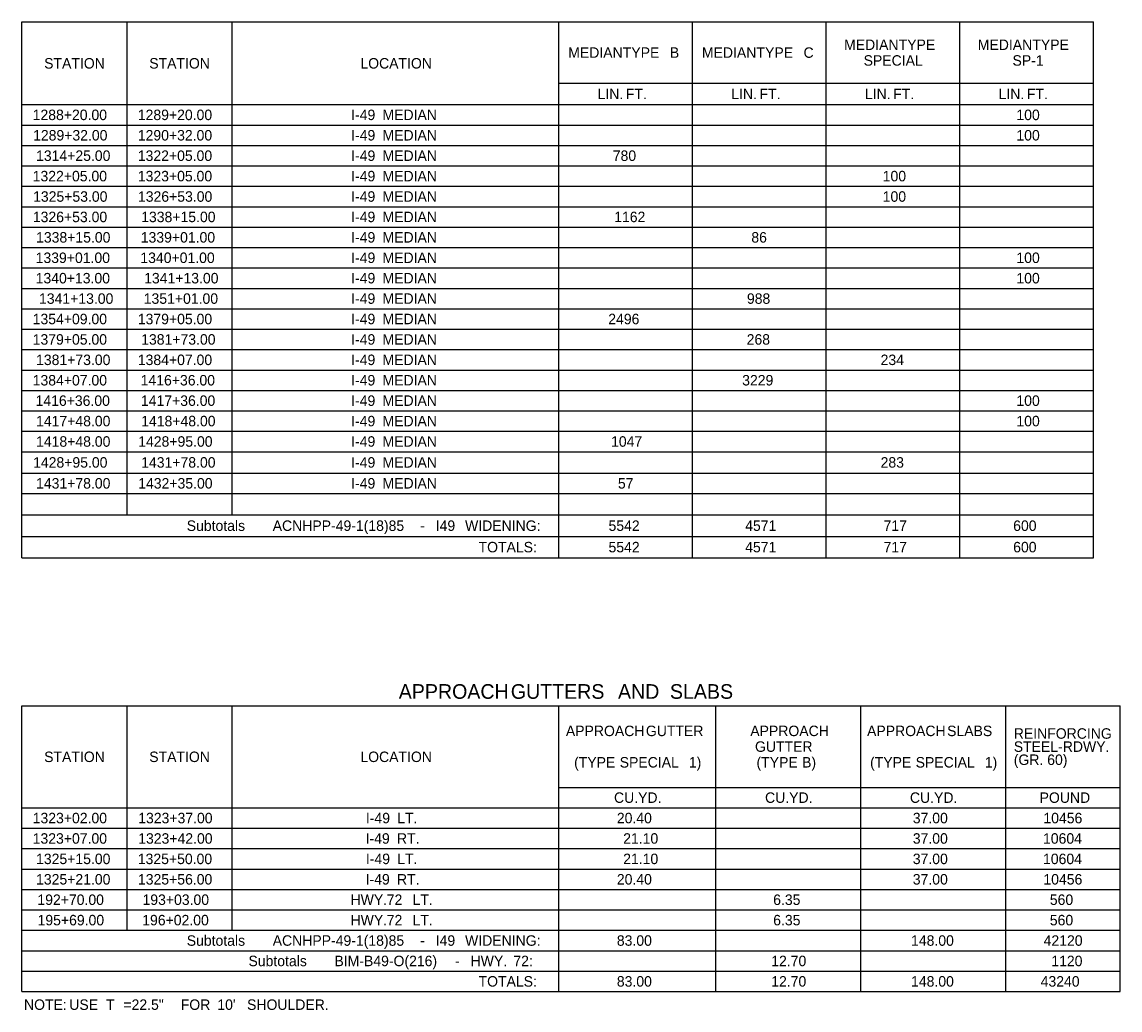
# Model space of a CAD drawing. Extents: x 1226589 to 1228130, y 151309 to 152305.
# Drawn here: x 1226589 to 1227113, y 151369 to 151841 of the extents above; entities that cross this region are included whole.
import ezdxf

# ---------------------------------------------------------------- set-up
doc = ezdxf.new("R2010")
doc.units = 0
doc.layers.add('R_Dimension', color=7, linetype='Continuous')

msp = doc.modelspace()

# ---------------------------------------------------------------- linework, layer by layer
at = {"layer": 'R_Dimension'}
for p, q in [((1226588.59, 151840.88), (1227100.46, 151840.88)), ((1226588.59, 151584.94), (1226588.59, 151840.88)), ((1226638.8, 151605.41), (1226638.8, 151840.88)), ((1226689.01, 151605.41), (1226689.01, 151840.88)), ((1226845.01, 151584.94), (1226845.01, 151840.88)), ((1226908.87, 151584.94), (1226908.87, 151840.88)), ((1226972.74, 151584.94), (1226972.74, 151840.88)), ((1227036.6, 151584.94), (1227036.6, 151840.88)), ((1227100.46, 151584.94), (1227100.46, 151840.88)), ((1226845.01, 151811.63), (1227100.46, 151811.63)), ((1226588.59, 151801.39), (1227100.46, 151801.39)), ((1226588.59, 151791.64), (1227100.46, 151791.64)), ((1226588.59, 151781.89), (1227100.46, 151781.89)), ((1226588.59, 151772.14), (1227100.46, 151772.14)), ((1226588.59, 151762.39), (1227100.46, 151762.39)), ((1226588.59, 151752.64), (1227100.46, 151752.64)), ((1226588.59, 151742.89), (1227100.46, 151742.89)), ((1226588.59, 151733.14), (1227100.46, 151733.14)), ((1226588.59, 151723.39), (1227100.46, 151723.39)), ((1226588.59, 151713.64), (1227100.46, 151713.64)), ((1226588.59, 151703.89), (1227100.46, 151703.89)), ((1226588.59, 151694.14), (1227100.46, 151694.14)), ((1226588.59, 151684.39), (1227100.46, 151684.39)), ((1226588.59, 151674.64), (1227100.46, 151674.64)), ((1226588.59, 151664.89), (1227100.46, 151664.89)), ((1226588.59, 151655.14), (1227100.46, 151655.14)), ((1226588.59, 151645.39), (1227100.46, 151645.39)), ((1226588.59, 151635.64), (1227100.46, 151635.64)), ((1226588.59, 151625.4), (1227100.46, 151625.4)), ((1226588.59, 151615.65), (1227100.46, 151615.65)), ((1226588.59, 151605.41), (1227100.46, 151605.41)), ((1226588.59, 151595.18), (1227100.46, 151595.18)), ((1226588.59, 151584.94), (1227100.46, 151584.94)), ((1226588.59, 151514.29), (1227113.14, 151514.29)), ((1226588.59, 151377.79), (1226588.59, 151514.29)), ((1226638.8, 151407.04), (1226638.8, 151514.29)), ((1226689.01, 151407.04), (1226689.01, 151514.29)), ((1226845.01, 151377.79), (1226845.01, 151514.29)), ((1226920.09, 151377.79), (1226920.09, 151514.29)), ((1226989.31, 151377.79), (1226989.31, 151514.29)), ((1227058.54, 151377.79), (1227058.54, 151514.29)), ((1227113.14, 151377.79), (1227113.14, 151514.29)), ((1226845.01, 151475.29), (1227113.14, 151475.29)), ((1226588.59, 151465.54), (1227113.14, 151465.54)), ((1226588.59, 151455.79), (1227113.14, 151455.79)), ((1226588.59, 151446.04), (1227113.14, 151446.04)), ((1226588.59, 151436.29), (1227113.14, 151436.29)), ((1226588.59, 151426.54), (1227113.14, 151426.54)), ((1226588.59, 151416.79), (1227113.14, 151416.79)), ((1226588.59, 151407.04), (1227113.14, 151407.04)), ((1226588.59, 151397.29), (1227113.14, 151397.29)), ((1226588.59, 151387.54), (1227113.14, 151387.54)), ((1226588.59, 151377.79), (1227113.14, 151377.79))]:
    msp.add_line(p, q, dxfattribs=at)

# ---------------------------------------------------------------- texts
for s, height, p in [('MEDIAN', 5, (1226981.32, 151827.5)), (' TYPE', 5, (1227005.53, 151827.5)), ('MEDIAN', 5, (1227045.18, 151827.5)), (' TYPE', 5, (1227069.4, 151827.5)), ('MEDIAN', 5, (1226849.54, 151823.75)), (' TYPE', 5, (1226873.75, 151823.75)), (' B', 5, (1226896.23, 151823.75)), ('MEDIAN', 5, (1226913.4, 151823.75)), (' TYPE', 5, (1226937.62, 151823.75)), (' C', 5, (1226960.1, 151823.75)), ('STATION', 5, (1226599.19, 151818.63)), ('STATION', 5, (1226649.4, 151818.63)), ('LOCATION', 5, (1226750.26, 151818.63)), ('SPECIAL', 5, (1226990.65, 151820)), ('SP-1', 5, (1227061.76, 151820)), ('LIN.', 5, (1226863.54, 151804.01)), (' FT.', 5, (1226875.19, 151804.01)), ('LIN.', 5, (1226927.4, 151804.01)), (' FT.', 5, (1226939.05, 151804.01)), ('LIN.', 5, (1226991.26, 151804.01)), (' FT.', 5, (1227002.92, 151804.01)), ('LIN.', 5, (1227055.13, 151804.01)), (' FT.', 5, (1227066.78, 151804.01)), ('1288+20.00', 5, (1226593.71, 151794.01)), ('1289+20.00', 5, (1226643.93, 151794.01)), ('I-49', 5, (1226745.85, 151794.01)), (' MEDIAN', 5, (1226758.96, 151794.01)), ('100', 5, (1227063.63, 151794.01)), ('1289+32.00', 5, (1226593.91, 151784.26)), ('1290+32.00', 5, (1226643.93, 151784.26)), ('I-49', 5, (1226745.85, 151784.26)), (' MEDIAN', 5, (1226758.96, 151784.26)), ('100', 5, (1227063.63, 151784.26)), ('1314+25.00', 5, (1226595.33, 151774.51)), ('1322+05.00', 5, (1226643.93, 151774.51)), ('I-49', 5, (1226745.85, 151774.51)), (' MEDIAN', 5, (1226758.96, 151774.51)), ('780', 5, (1226870.82, 151774.51)), ('1322+05.00', 5, (1226593.71, 151764.76)), ('1323+05.00', 5, (1226643.93, 151764.76)), ('I-49', 5, (1226745.85, 151764.76)), (' MEDIAN', 5, (1226758.96, 151764.76)), ('100', 5, (1226999.77, 151764.76)), ('1325+53.00', 5, (1226593.91, 151755.01)), ('1326+53.00', 5, (1226644, 151755.01)), ('I-49', 5, (1226745.85, 151755.01)), (' MEDIAN', 5, (1226758.96, 151755.01)), ('100', 5, (1226999.77, 151755.01)), ('1326+53.00', 5, (1226593.79, 151745.26)), ('1338+15.00', 5, (1226645.54, 151745.26)), ('I-49', 5, (1226745.85, 151745.26)), (' MEDIAN', 5, (1226758.96, 151745.26)), ('1162', 5, (1226871.51, 151745.26)), ('1338+15.00', 5, (1226595.33, 151735.51)), ('1339+01.00', 5, (1226645.34, 151735.51)), ('I-49', 5, (1226745.85, 151735.51)), (' MEDIAN', 5, (1226758.96, 151735.51)), ('86', 5, (1226937.01, 151735.51)), ('1339+01.00', 5, (1226595.13, 151725.76)), ('1340+01.00', 5, (1226645.15, 151725.76)), ('I-49', 5, (1226745.85, 151725.76)), (' MEDIAN', 5, (1226758.96, 151725.76)), ('100', 5, (1227063.63, 151725.76)), ('1340+13.00', 5, (1226595.13, 151716.01)), ('1341+13.00', 5, (1226646.96, 151716.01)), ('I-49', 5, (1226745.85, 151716.01)), (' MEDIAN', 5, (1226758.96, 151716.01)), ('100', 5, (1227063.63, 151716.01)), ('1341+13.00', 5, (1226596.74, 151706.26)), ('1351+01.00', 5, (1226646.76, 151706.26)), ('I-49', 5, (1226745.85, 151706.26)), (' MEDIAN', 5, (1226758.96, 151706.26)), ('988', 5, (1226934.9, 151706.26)), ('1354+09.00', 5, (1226593.71, 151696.51)), ('1379+05.00', 5, (1226643.93, 151696.51)), ('I-49', 5, (1226745.85, 151696.51)), (' MEDIAN', 5, (1226758.96, 151696.51)), ('2496', 5, (1226868.66, 151696.51)), ('1379+05.00', 5, (1226593.71, 151686.76)), ('1381+73.00', 5, (1226645.54, 151686.76)), ('I-49', 5, (1226745.85, 151686.76)), (' MEDIAN', 5, (1226758.96, 151686.76)), ('268', 5, (1226934.78, 151686.76)), ('1381+73.00', 5, (1226595.33, 151677.01)), ('1384+07.00', 5, (1226643.93, 151677.01)), ('I-49', 5, (1226745.85, 151677.01)), (' MEDIAN', 5, (1226758.96, 151677.01)), ('234', 5, (1226998.76, 151677.01)), ('1384+07.00', 5, (1226593.71, 151667.26)), ('1416+36.00', 5, (1226645.3, 151667.26)), ('I-49', 5, (1226745.85, 151667.26)), (' MEDIAN', 5, (1226758.96, 151667.26)), ('3229', 5, (1226932.64, 151667.26)), ('1416+36.00', 5, (1226595.09, 151657.51)), ('1417+36.00', 5, (1226645.42, 151657.51)), ('I-49', 5, (1226745.85, 151657.51)), (' MEDIAN', 5, (1226758.96, 151657.51)), ('100', 5, (1227063.63, 151657.51)), ('1417+48.00', 5, (1226595.33, 151647.76)), ('1418+48.00', 5, (1226645.54, 151647.76)), ('I-49', 5, (1226745.85, 151647.76)), (' MEDIAN', 5, (1226758.96, 151647.76)), ('100', 5, (1227063.63, 151647.76)), ('1418+48.00', 5, (1226595.33, 151638.01)), ('1428+95.00', 5, (1226644.12, 151638.01)), ('I-49', 5, (1226745.85, 151638.01)), (' MEDIAN', 5, (1226758.96, 151638.01)), ('1047', 5, (1226870.01, 151638.01)), ('1428+95.00', 5, (1226593.91, 151628.02)), ('1431+78.00', 5, (1226645.54, 151628.02)), ('I-49', 5, (1226745.85, 151628.02)), (' MEDIAN', 5, (1226758.96, 151628.02)), ('283', 5, (1226998.76, 151628.02)), ('1431+78.00', 5, (1226595.33, 151618.03)), ('1432+35.00', 5, (1226644.12, 151618.03)), ('I-49', 5, (1226745.85, 151618.03)), (' MEDIAN', 5, (1226758.96, 151618.03)), ('57', 5, (1226873.28, 151618.03)), ('Subtotals', 5, (1226667.3, 151597.8)), (' ACNHPP-49-1(18)85', 5, (1226706.51, 151597.8)), (' I49', 5, (1226784.39, 151597.8)), (' WIDENING:', 5, (1226798.4, 151597.8)), ('5542', 5, (1226868.79, 151597.8)), ('4571', 5, (1226934.07, 151597.8)), ('717', 5, (1227000.18, 151597.8)), ('600', 5, (1227062.09, 151597.8)), (' -', 5, (1226776.95, 151597.8)), ('TOTALS:', 5, (1226806.71, 151587.56)), ('5542', 5, (1226868.79, 151587.56)), ('4571', 5, (1226934.07, 151587.56)), ('717', 5, (1227000.18, 151587.56)), ('600', 5, (1227062.09, 151587.56)), ('APPROACH', 7, (1226768.57, 151517.61)), (' GUTTERS', 7, (1226819.5, 151517.61)), (' AND', 7, (1226870.7, 151517.61)), (' SLABS', 7, (1226895.51, 151517.61)), ('APPROACH', 5, (1226848.42, 151499.79)), (' GUTTER', 5, (1226884.79, 151499.79)), ('APPROACH', 5, (1226936.51, 151499.79)), ('APPROACH', 5, (1226992.29, 151499.79)), (' SLABS', 5, (1227028.67, 151499.79)), ('REINFORCING', 5, (1227062.38, 151498.54)), ('GUTTER', 5, (1226938.76, 151492.29)), ('STEEL-RDWY.', 5, (1227062.38, 151492.28)), ('STATION', 5, (1226599.19, 151487.41)), ('STATION', 5, (1226649.4, 151487.41)), ('LOCATION', 5, (1226750.26, 151487.41)), ('(TYPE', 5, (1226852.35, 151484.79)), (' 1)', 5, (1226905.31, 151484.79)), ('(TYPE', 5, (1226939.48, 151484.79)), (' B)', 5, (1226959.4, 151484.79)), ('(TYPE', 5, (1226993.73, 151484.79)), (' 1)', 5, (1227046.68, 151484.79)), ('(GR. 60)', 5, (1227062.38, 151486.02)), (' SPECIAL', 5, (1226872.27, 151484.79)), (' SPECIAL', 5, (1227013.65, 151484.79)), ('CU.YD.', 5, (1226871.41, 151467.91)), ('CU.YD.', 5, (1226943.56, 151467.91)), ('CU.YD.', 5, (1227012.78, 151467.91)), ('POUND', 5, (1227074.72, 151467.91)), ('1323+02.00', 5, (1226593.71, 151458.16)), ('1323+37.00', 5, (1226644.12, 151458.16)), ('I-49', 5, (1226752.88, 151458.16)), (' LT.', 5, (1226765.99, 151458.16)), ('20.40', 5, (1226872.77, 151458.16)), ('37.00', 5, (1227014.14, 151458.16)), ('10456', 5, (1227076.53, 151458.16)), ('1323+07.00', 5, (1226593.71, 151448.41)), ('1323+42.00', 5, (1226644.12, 151448.41)), ('I-49', 5, (1226752.76, 151448.41)), (' RT.', 5, (1226765.87, 151448.41)), ('21.10', 5, (1226875.8, 151448.41)), ('37.00', 5, (1227014.14, 151448.41)), ('10604', 5, (1227076.35, 151448.41)), ('1325+15.00', 5, (1226595.33, 151438.66)), ('1325+50.00', 5, (1226643.93, 151438.66)), ('I-49', 5, (1226752.88, 151438.66)), (' LT.', 5, (1226765.99, 151438.66)), ('21.10', 5, (1226875.8, 151438.66)), ('37.00', 5, (1227014.14, 151438.66)), ('10604', 5, (1227076.35, 151438.66)), ('1325+21.00', 5, (1226595.33, 151428.91)), ('1325+56.00', 5, (1226644, 151428.91)), ('I-49', 5, (1226752.76, 151428.91)), (' RT.', 5, (1226765.87, 151428.91)), ('20.40', 5, (1226872.77, 151428.91)), ('37.00', 5, (1227014.14, 151428.91)), ('10456', 5, (1227076.53, 151428.91)), ('192+70.00', 5, (1226595.96, 151419.16)), ('193+03.00', 5, (1226646.17, 151419.16)), ('HWY.', 5, (1226745.56, 151419.16)), (' 72', 5, (1226760.99, 151419.16)), (' LT.', 5, (1226773.31, 151419.16)), ('6.35', 5, (1226947.46, 151419.16)), ('560', 5, (1227079.6, 151419.16)), ('195+69.00', 5, (1226596.04, 151409.41)), ('196+02.00', 5, (1226646.05, 151409.41)), ('HWY.', 5, (1226745.56, 151409.41)), (' 72', 5, (1226760.99, 151409.41)), (' LT.', 5, (1226773.31, 151409.41)), ('6.35', 5, (1226947.46, 151409.41)), ('560', 5, (1227079.6, 151409.41)), ('Subtotals', 5, (1226667.3, 151399.66)), (' ACNHPP-49-1(18)85', 5, (1226706.51, 151399.66)), (' -', 5, (1226776.95, 151399.66)), (' I49', 5, (1226784.39, 151399.66)), (' WIDENING:', 5, (1226798.4, 151399.66)), ('83.00', 5, (1226872.77, 151399.66)), ('148.00', 5, (1227013.31, 151399.66)), ('42120', 5, (1227076.64, 151399.66)), ('Subtotals', 5, (1226696.79, 151389.91)), (' BIM-B49-O(216)', 5, (1226736, 151389.91)), (' -', 5, (1226793.6, 151389.91)), (' HWY.', 5, (1226801.04, 151389.91)), (' 72:', 5, (1226821.47, 151389.91)), ('12.70', 5, (1226946.53, 151389.91)), ('1120', 5, (1227080.31, 151389.91)), ('TOTALS:', 5, (1226806.71, 151380.16)), ('83.00', 5, (1226872.77, 151380.16)), ('12.70', 5, (1226946.53, 151380.16)), ('148.00', 5, (1227013.31, 151380.16)), ('43240', 5, (1227075.23, 151380.16)), ('NOTE:', 5, (1226589.56, 151369.04)), (' USE', 5, (1226609.33, 151369.04)), (' T', 5, (1226626.92, 151369.04)), (' =22.5"', 5, (1226635.19, 151369.04)), (' FOR', 5, (1226662.59, 151369.04)), (" 10'", 5, (1226680.07, 151369.04)), ('  SHOULDER.', 5, (1226692.4, 151369.04))]:
    msp.add_text(s, height=height, dxfattribs=at).set_placement(p)

doc.saveas('drawing.dxf')
